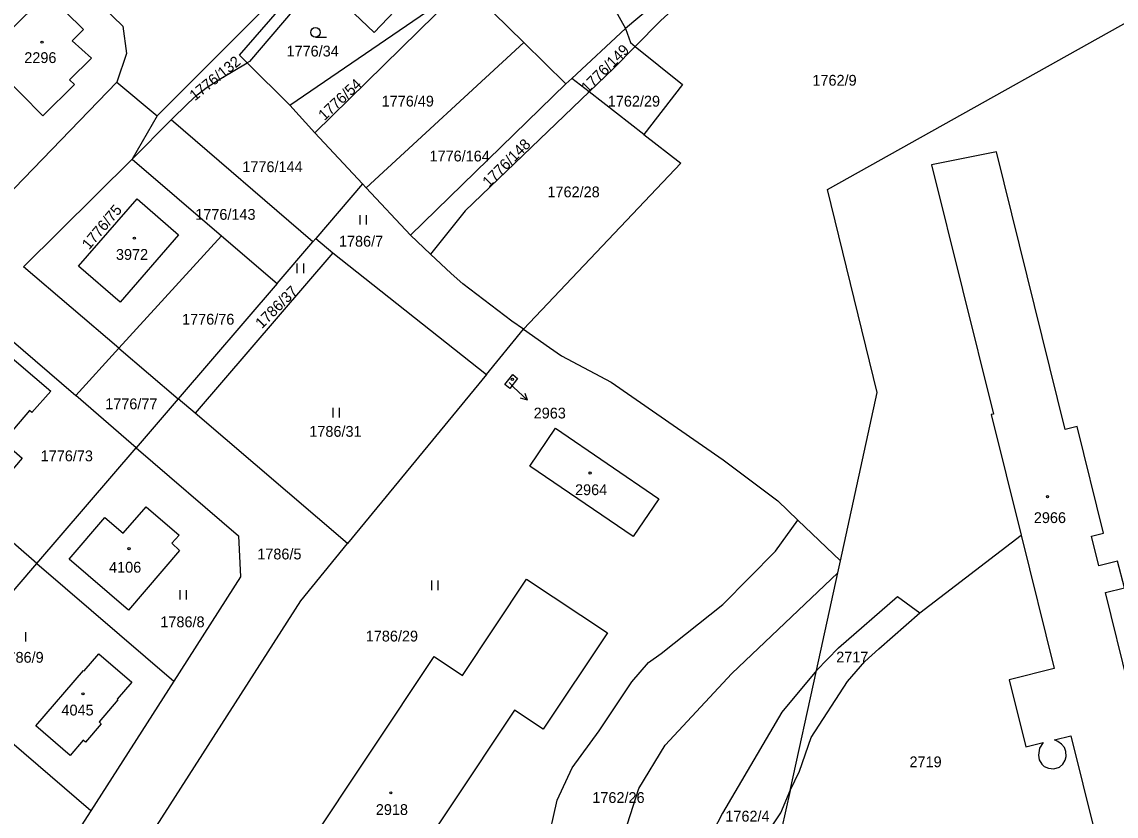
# Model space of a CAD drawing. Extents: x -679220 to -673243, y -1075091 to -1066557.
# Drawn here: x -676725.7 to -676553.6, y -1072526 to -1072401 of the extents above; entities that cross this region are included whole.
import ezdxf

# ---------------------------------------------------------------- set-up
doc = ezdxf.new("R2010")
doc.units = 0
for name, color, linetype in [('Hranice parcel', 7, 'Continuous'), ('Parcelní čísla', 7, 'Continuous'), ('Pop  PČ popisy', 7, 'Continuous'), ('Značky budov', 7, 'Continuous'), ('Značky kultur', 7, 'Continuous')]:
    doc.layers.add(name, color=color, linetype=linetype)

msp = doc.modelspace()

# ---------------------------------------------------------------- linework, layer by layer
at = {"layer": 'Hranice parcel'}
for p, q in [((-676704.44, -1072415.85), (-676669.29, -1072380.6)), ((-676641.13, -1072383.33), (-676630.75, -1072402.09)), ((-676670.33, -1072384.08), (-676689.91, -1072407.26)), ((-676683.56, -1072414.13), (-676655.95, -1072395.26)), ((-676655.95, -1072395.26), (-676679.66, -1072418.48)), ((-676646.74, -1072404.3), (-676655.95, -1072395.26)), ((-676621.59, -1072394.33), (-676630.75, -1072402.09)), ((-676630.75, -1072402.09), (-676639.23, -1072409.95)), ((-676671.57, -1072427.14), (-676646.74, -1072404.3)), ((-676640.13, -1072410.78), (-676646.74, -1072404.3)), ((-676629.22, -1072404.9), (-676621.77, -1072410.89)), ((-676694.43, -1072409.95), (-676690.29, -1072407.5)), ((-676689.91, -1072407.26), (-676690.29, -1072407.5)), ((-676690.29, -1072407.5), (-676683.56, -1072414.13)), ((-676728.36, -1072428.71), (-676710.78, -1072410.52)), ((-676710.78, -1072410.52), (-676704.44, -1072415.85)), ((-676640.13, -1072410.78), (-676664.59, -1072434.61)), ((-676639.23, -1072409.95), (-676640.13, -1072410.78)), ((-676636.5, -1072412.07), (-676639.23, -1072409.95)), ((-676621.77, -1072410.89), (-676627.86, -1072418.76)), ((-676627.86, -1072418.76), (-676636.5, -1072412.07)), ((-676679.66, -1072418.48), (-676683.56, -1072414.13)), ((-676704.44, -1072415.85), (-676708.38, -1072422.62)), ((-676708.38, -1072422.62), (-676702.25, -1072416.45)), ((-676679.94, -1072435.63), (-676702.25, -1072416.45)), ((-676679.66, -1072418.48), (-676672.14, -1072426.53)), ((-676627.86, -1072418.76), (-676622.04, -1072423.27)), ((-676708.38, -1072422.62), (-676694.33, -1072434.69)), ((-676622.04, -1072423.27), (-676646.79, -1072449.4)), ((-676672.14, -1072426.53), (-676679.49, -1072435.1)), ((-676672.14, -1072426.53), (-676671.57, -1072427.14)), ((-676664.59, -1072434.61), (-676671.57, -1072427.14)), ((-676710.47, -1072452.39), (-676694.33, -1072434.69)), ((-676694.33, -1072434.69), (-676685.58, -1072442.2)), ((-676679.94, -1072435.63), (-676679.49, -1072435.1)), ((-676679.49, -1072435.1), (-676676.8, -1072437.35)), ((-676661.44, -1072437.58), (-676664.59, -1072434.61)), ((-676685.58, -1072442.2), (-676679.94, -1072435.63)), ((-676676.8, -1072437.35), (-676698.49, -1072462.62)), ((-676676.8, -1072437.35), (-676652.62, -1072456.51)), ((-676685.58, -1072442.2), (-676701.15, -1072460.35)), ((-676652.62, -1072456.51), (-676646.79, -1072449.4)), ((-676717.26, -1072459.84), (-676710.47, -1072452.39)), ((-676710.47, -1072452.39), (-676701.15, -1072460.35)), ((-676652.62, -1072456.51), (-676674.49, -1072483.12)), ((-676707.74, -1072468.04), (-676717.26, -1072459.84)), ((-676701.15, -1072460.35), (-676707.74, -1072468.04)), ((-676698.49, -1072462.62), (-676701.15, -1072460.35)), ((-676674.49, -1072483.12), (-676698.49, -1072462.62)), ((-676723.37, -1072486.22), (-676747.67, -1072465.34)), ((-676723.37, -1072486.22), (-676707.74, -1072468.04)), ((-676603.66, -1072479.4), (-676596.95, -1072485.83)), ((-676584.47, -1072493.98), (-676568.52, -1072481.8)), ((-676739.04, -1072504.4), (-676723.37, -1072486.22)), ((-676723.37, -1072486.22), (-676701.82, -1072504.74)), ((-676597.36, -1072487.7), (-676596.95, -1072485.83)), ((-676600.72, -1072503.07), (-676597.36, -1072487.7)), ((-676604.84, -1072521.96), (-676600.72, -1072503.07)), ((-676714.91, -1072525.16), (-676739.04, -1072504.4)), ((-676701.82, -1072504.74), (-676714.91, -1072525.16)), ((-676714.91, -1072525.16), (-676724.45, -1072540.03))]:
    msp.add_line(p, q, dxfattribs=at)
for points in [[(-676629.22, -1072404.9), (-676625.24, -1072400.86), (-676614.32, -1072390.86), (-676607.81, -1072386.16), (-676592.35, -1072371.56)], [(-676690.29, -1072407.5), (-676691.5, -1072406.3), (-676671.12, -1072382.77)], [(-676670.76, -1072387.26), (-676663.9, -1072393.85), (-676666.01, -1072396.05), (-676664.98, -1072397.03), (-676670.29, -1072402.73), (-676674.48, -1072398.75), (-676673.66, -1072397.9), (-676677.45, -1072394.29), (-676670.76, -1072387.26)], [(-676720.87, -1072391), (-676709.86, -1072401.72), (-676709.28, -1072406.04), (-676710.78, -1072410.52)], [(-676596.95, -1072485.83), (-676591.17, -1072459.32), (-676598.96, -1072427.43), (-676538.2, -1072393.4), (-676534.79, -1072393.04), (-676524.1, -1072390.75)], [(-676717.48, -1072410.92), (-676718.23, -1072410.16), (-676714.79, -1072406.75), (-676717.84, -1072404.04), (-676716.06, -1072402.24), (-676721.76, -1072396.6), (-676728.28, -1072403.07), (-676729.3, -1072402.04), (-676732.74, -1072405.46), (-676722.43, -1072415.84), (-676717.48, -1072410.92)], [(-676630.75, -1072402.09), (-676629.99, -1072404.29), (-676629.22, -1072404.9)], [(-676629.22, -1072404.9), (-676632.61, -1072408.34), (-676636.5, -1072412.07)], [(-676702.25, -1072416.45), (-676699.62, -1072413.91), (-676698.14, -1072412.54), (-676696.57, -1072411.3), (-676694.43, -1072409.95)], [(-676636.5, -1072412.07), (-676655.99, -1072430.75), (-676661.44, -1072437.58)], [(-676552.26, -1072490.08), (-676553.34, -1072485.9), (-676556.27, -1072486.62), (-676557.43, -1072481.93), (-676555.57, -1072481.47), (-676559.68, -1072464.69), (-676561.57, -1072465.16), (-676572.37, -1072421.48), (-676582.59, -1072423.55), (-676572.87, -1072462.74), (-676573.23, -1072462.83), (-676568.52, -1072481.8)], [(-676710.47, -1072452.39), (-676725.51, -1072439.56), (-676708.38, -1072422.62)], [(-676707.61, -1072428.88), (-676701.11, -1072434.52), (-676710.3, -1072445.13), (-676716.81, -1072439.48), (-676707.61, -1072428.88)], [(-676646.79, -1072449.4), (-676648.66, -1072448.11), (-676656.36, -1072442.26), (-676658.18, -1072440.65), (-676661.44, -1072437.58)], [(-676747.67, -1072465.34), (-676731.99, -1072447.16), (-676717.26, -1072459.84)], [(-676646.79, -1072449.4), (-676642.72, -1072452.29), (-676640.83, -1072453.58), (-676633.01, -1072457.73), (-676615.42, -1072469.96), (-676606.79, -1072476.4), (-676603.66, -1072479.4)], [(-676724.18, -1072462.5), (-676724.53, -1072462.2), (-676728.69, -1072467.07), (-676725.69, -1072469.68), (-676729.35, -1072473.94), (-676739.88, -1072464.93), (-676729.09, -1072452.36), (-676721.18, -1072459.11), (-676724.18, -1072462.5)], [(-676648.51, -1072456.53), (-676647.74, -1072457.16), (-676648.98, -1072458.71), (-676649.76, -1072458.08), (-676648.51, -1072456.53)], [(-676629.58, -1072482.02), (-676645.81, -1072470.94), (-676641.79, -1072464.97), (-676625.53, -1072476.08), (-676629.58, -1072482.02)], [(-676707.74, -1072468.04), (-676691.68, -1072481.89), (-676691.32, -1072488.35), (-676701.82, -1072504.74)], [(-676718.29, -1072485.58), (-676712.67, -1072479.02), (-676709.82, -1072481.49), (-676706.19, -1072477.31), (-676700.99, -1072481.81), (-676702.15, -1072483.04), (-676700.92, -1072484.2), (-676708.96, -1072493.59), (-676718.29, -1072485.58)], [(-676663.59, -1072581.27), (-676657.41, -1072570.77), (-676648.78, -1072552.8), (-676645.39, -1072542.5), (-676643.86, -1072534.39), (-676643.14, -1072530.69), (-676641.49, -1072523.46), (-676639.13, -1072518.4), (-676634.89, -1072512.54), (-676629.79, -1072504.85), (-676627.14, -1072501.83), (-676625.14, -1072500.4), (-676615.43, -1072492.7), (-676607.18, -1072484.29), (-676603.66, -1072479.4)], [(-676568.52, -1072481.8), (-676563.31, -1072502.78), (-676570.38, -1072504.54), (-676567.76, -1072515.09), (-676565.06, -1072514.42), (-676565.6, -1072515.28), (-676565.76, -1072516.37), (-676565.65, -1072517.13), (-676565.26, -1072517.79), (-676564.87, -1072518.15), (-676564.21, -1072518.45), (-676563.39, -1072518.56), (-676562.46, -1072518.26), (-676561.94, -1072517.81), (-676561.6, -1072517.17), (-676561.44, -1072516.58), (-676561.46, -1072515.81), (-676561.71, -1072515.21), (-676562.14, -1072514.65), (-676562.73, -1072514.24), (-676563.28, -1072513.96), (-676560.7, -1072513.34), (-676549.28, -1072559.4)], [(-676716.17, -1072545.65), (-676681.84, -1072492.09), (-676674.49, -1072483.12)], [(-676648.22, -1072509.32), (-676678.27, -1072554.47), (-676690.94, -1072546.04), (-676660.88, -1072500.87), (-676656.39, -1072503.85), (-676646.35, -1072488.7), (-676633.62, -1072497.13), (-676643.73, -1072512.29), (-676648.22, -1072509.32)], [(-676652.02, -1072569.87), (-676645.24, -1072557.85), (-676641.08, -1072548.9), (-676633.13, -1072535.51), (-676628.68, -1072521.66), (-676624.52, -1072514.82), (-676614.05, -1072503.52), (-676597.36, -1072487.7)], [(-676551.61, -1072505.48), (-676555.23, -1072490.82), (-676552.26, -1072490.08)], [(-676600.72, -1072503.07), (-676597.25, -1072499.5), (-676587.99, -1072491.42), (-676584.47, -1072493.98)], [(-676604.84, -1072521.96), (-676603.36, -1072518.9), (-676601.57, -1072513.59), (-676595.85, -1072504.79), (-676593.1, -1072501.68), (-676590.9, -1072499.69), (-676584.47, -1072493.98)], [(-676710.62, -1072507.7), (-676713.59, -1072511.13), (-676713.26, -1072511.47), (-676715.75, -1072514.32), (-676716.11, -1072514.03), (-676718.17, -1072516.44), (-676723.55, -1072511.8), (-676716.05, -1072503.05), (-676715.93, -1072503.14), (-676713.64, -1072500.47), (-676708.45, -1072504.93), (-676710.73, -1072507.59), (-676710.62, -1072507.7)], [(-676600.72, -1072503.07), (-676606.15, -1072509.65), (-676615.52, -1072525.52), (-676623.12, -1072540.2), (-676630.2, -1072558.24), (-676644.99, -1072583.54), (-676650.25, -1072589.43)], [(-676647.52, -1072592.64), (-676644.91, -1072590.08), (-676641.41, -1072587.12), (-676639.91, -1072585.27), (-676637.38, -1072578.92), (-676629.15, -1072564.42), (-676622.89, -1072551.66), (-676618.62, -1072544.59), (-676613.89, -1072536.85), (-676606.32, -1072525.48), (-676604.84, -1072521.96)], [(-676604.84, -1072521.96), (-676607.57, -1072534.09), (-676599.06, -1072565.36)]]:
    msp.add_lwpolyline(points, dxfattribs=at)
at = {"layer": 'Pop  PČ popisy'}
for p, q in [((-676649.08, -1072457.79), (-676648.36, -1072458.49)), ((-676648.36, -1072458.49), (-676646.2, -1072460.57)), ((-676646.2, -1072460.57), (-676646.57, -1072459.52)), ((-676646.2, -1072460.57), (-676647.27, -1072460.24))]:
    msp.add_line(p, q, dxfattribs=at)
at = {"layer": 'Značky budov'}
for centre in [(-676722.57, -1072404.24), (-676708.03, -1072435.07), (-676648.56, -1072457.26), (-676636.33, -1072472.01), (-676564.36, -1072475.74), (-676708.88, -1072483.91), (-676716.13, -1072506.74), (-676667.68, -1072522.31)]:
    msp.add_circle(centre, 0.175, dxfattribs=at)
at = {"layer": 'Značky kultur'}
for p, q in [((-676679.55, -1072403.44), (-676677.8, -1072403.44)), ((-676672.52, -1072432.94), (-676672.52, -1072431.44)), ((-676671.52, -1072432.94), (-676671.52, -1072431.44)), ((-676682.4, -1072440.57), (-676682.4, -1072439.07)), ((-676681.4, -1072440.57), (-676681.4, -1072439.07)), ((-676676.77, -1072463.26), (-676676.77, -1072461.76)), ((-676675.77, -1072463.26), (-676675.77, -1072461.76)), ((-676700.85, -1072491.92), (-676700.85, -1072490.42)), ((-676699.85, -1072491.92), (-676699.85, -1072490.42)), ((-676661.26, -1072490.42), (-676661.26, -1072488.92)), ((-676660.26, -1072490.42), (-676660.26, -1072488.92)), ((-676725.14, -1072498.52), (-676725.14, -1072497.02))]:
    msp.add_line(p, q, dxfattribs=at)
msp.add_circle((-676679.55, -1072402.69), 0.75, dxfattribs=at)

# ---------------------------------------------------------------- texts
at = {"layer": 'Parcelní čísla'}
for s, p in [('2296', (-676725.36, -1072407.52)), ('1776/34', (-676684.1, -1072406.49)), ('1762/9', (-676601.35, -1072411.08)), ('1776/49', (-676669.13, -1072414.36)), ('1762/29', (-676633.55, -1072414.37)), ('1776/164', (-676661.6, -1072423)), ('1776/144', (-676691.05, -1072424.68)), ('1762/28', (-676643.04, -1072428.64)), ('1776/143', (-676698.46, -1072432.18)), ('1786/7', (-676675.85, -1072436.4)), ('3972', (-676710.94, -1072438.48)), ('1776/76', (-676700.53, -1072448.67)), ('1776/77', (-676712.63, -1072461.98)), ('2963', (-676645.21, -1072463.43)), ('1786/31', (-676680.51, -1072466.31)), ('1776/73', (-676722.78, -1072470.16)), ('2964', (-676638.7, -1072475.49)), ('2966', (-676566.51, -1072479.88)), ('1786/5', (-676688.7, -1072485.6)), ('4106', (-676712.02, -1072487.68)), ('1786/8', (-676703.95, -1072496.27)), ('1786/29', (-676671.63, -1072498.51)), ('1786/9', (-676729.27, -1072501.85)), ('2717', (-676597.61, -1072501.81)), ('4045', (-676719.51, -1072510.15)), ('2719', (-676586.08, -1072518.29)), ('1762/26', (-676635.98, -1072523.91)), ('2918', (-676670.05, -1072525.8)), ('1762/4', (-676615.05, -1072526.84))]:
    msp.add_text(s, height=1.7, dxfattribs=at).set_placement(p)
for s, rotation, p in [('1776/149', 45, (-676636.74, -1072412.33)), ('1776/132', 39, (-676698.52, -1072413.55)), ('1776/54', 43, (-676678.14, -1072416.66)), ('1776/148', 45, (-676652.26, -1072427.17)), ('1776/75', 50, (-676715.16, -1072436.99)), ('1786/37', 45, (-676688, -1072449.4))]:
    msp.add_text(s, height=1.7, rotation=rotation, dxfattribs=at).set_placement(p)

doc.saveas('drawing.dxf')
